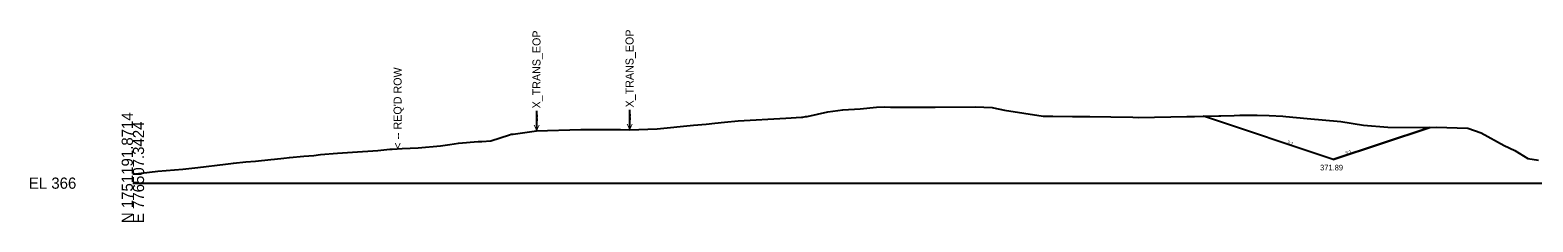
# Model space of a CAD drawing. Extents: x 776426 to 854588, y 1736205 to 1756790.
# Drawn here: x 805845.1 to 806220.7, y 1738705.1 to 1738753 of the extents above; entities that cross this region are included whole.
import ezdxf

# ---------------------------------------------------------------- set-up
doc = ezdxf.new("R2010")
doc.units = 0
for name, color, linetype in [('DTM CONTOURS_MAJOR_TX', 7, 'Continuous'), ('DTM_X_FLOW_ARROWS', 7, 'Continuous'), ('X_TRANS_EOP', 7, 'Continuous'), ('XS_M_SHAPES_EARTHWORK', 7, 'Continuous'), ('XS_P_FINISHED_GRADE', 7, 'Continuous'), ('XS_P_ROW', 7, 'Continuous'), ('XS_P_TX_DCH', 7, 'Continuous'), ('XS_P_TX_FS_BS', 7, 'Continuous'), ('XS_X_PAVEMENT', 7, 'Continuous')]:
    doc.layers.add(name, color=color, linetype=linetype)

msp = doc.modelspace()

# ---------------------------------------------------------------- linework, layer by layer
at = {"layer": 'DTM CONTOURS_MAJOR_TX'}
msp.add_line((805870.79, 1738714.76), (806370.79, 1738714.76), dxfattribs=at)
at = {"layer": 'DTM_X_FLOW_ARROWS'}
msp.add_lwpolyline([(805870.79, 1738716.99), (805877.07, 1738717.73), (805883.26, 1738718.29), (805887.07, 1738718.7), (805893.93, 1738719.48), (805895.96, 1738719.75), (805899.04, 1738720.09), (805901.42, 1738720.27), (805905.3, 1738720.68), (805906.17, 1738720.74), (805908.51, 1738720.99), (805909.98, 1738721.18), (805913.48, 1738721.54), (805915.98, 1738721.7), (805917.67, 1738721.89), (805921.95, 1738722.23), (805925.67, 1738722.52), (805932.01, 1738722.95), (805935, 1738723.24), (805935.57, 1738723.29), (805938.13, 1738723.4), (805942.09, 1738723.61), (805947.69, 1738724.1), (805950.03, 1738724.43), (805952.16, 1738724.76), (805957.1, 1738725.14), (805958.01, 1738725.18), (805960.29, 1738725.35), (805964.95, 1738726.86), (805965.38, 1738726.99), (805965.81, 1738727.04), (805971.67, 1738727.87), (805982.74, 1738728.13), (805983.23, 1738728.14), (805983.58, 1738728.14), (805984.55, 1738728.14), (805992.69, 1738728.13), (805994.92, 1738728.11), (806001.81, 1738728.34), (806010.92, 1738729.23), (806014.09, 1738729.53), (806016.27, 1738729.77), (806018.68, 1738729.99), (806022.1, 1738730.35), (806034.01, 1738730.99), (806037.88, 1738731.25), (806038.26, 1738731.26), (806038.91, 1738731.38), (806039.31, 1738731.44), (806044.51, 1738732.6), (806048.25, 1738733.08), (806052.55, 1738733.32), (806056.62, 1738733.74), (806058.71, 1738733.86), (806060.12, 1738733.77), (806071.32, 1738733.74), (806081.34, 1738733.82), (806083.44, 1738733.78), (806085.54, 1738733.66), (806085.86, 1738733.58), (806088.65, 1738733.02), (806098.32, 1738731.53), (806099.03, 1738731.53), (806099.85, 1738731.54), (806100.3, 1738731.52), (806100.74, 1738731.5), (806105.63, 1738731.45), (806109.96, 1738731.43), (806115.24, 1738731.36), (806120.7, 1738731.24), (806122.12, 1738731.17), (806134.17, 1738731.44), (806136.13, 1738731.4), (806146.05, 1738731.69), (806147.49, 1738731.73), (806150.87, 1738731.79), (806151.77, 1738731.79), (806154.8, 1738731.67), (806158.16, 1738731.48), (806158.93, 1738731.43), (806164.27, 1738730.95), (806172.72, 1738730.14), (806178.32, 1738729.25), (806184.43, 1738728.79), (806193.19, 1738728.65), (806196.5, 1738728.74), (806204.41, 1738728.54), (806207.75, 1738727.3), (806213.5, 1738724.14), (806216.14, 1738722.92), (806219.47, 1738720.93), (806222.08, 1738720.47)], dxfattribs=at)
at = {"layer": 'X_TRANS_EOP'}
for p, q in [((805971.67, 1738732.87), (805971.67, 1738727.87)), ((805971.67, 1738732.87), (805971.67, 1738727.87)), ((805994.92, 1738733.11), (805994.92, 1738728.11)), ((805994.92, 1738733.11), (805994.92, 1738728.11))]:
    msp.add_line(p, q, dxfattribs=at)
at = {"layer": 'XS_M_SHAPES_EARTHWORK'}
msp.add_lwpolyline([(806154.8, 1738731.67), (806158.16, 1738731.48), (806158.93, 1738731.43), (806164.27, 1738730.95), (806172.72, 1738730.14), (806178.32, 1738729.25), (806184.43, 1738728.79), (806193.19, 1738728.65), (806194.94, 1738728.7), (806170.79, 1738720.65), (806138.35, 1738731.47), (806146.05, 1738731.69), (806147.49, 1738731.73), (806150.87, 1738731.79), (806151.77, 1738731.79)], close=True, dxfattribs=at)
at = {"layer": 'XS_P_FINISHED_GRADE'}
for q in [(806138.35, 1738731.47), (806194.94, 1738728.7)]:
    msp.add_line((806170.79, 1738720.65), q, dxfattribs=at)

# ---------------------------------------------------------------- texts
at = {"layer": 'DTM CONTOURS_MAJOR_TX'}
for s, p in [('N 1751191.8714', (805870.79, 1738704.76)), ('E 776507.3424', (805873.59, 1738704.76))]:
    msp.add_text(s, height=2.8, rotation=90, dxfattribs=at).set_placement(p)
msp.add_text('EL 366', height=2.8, dxfattribs=at).set_placement((805844.79, 1738713.36))
at = {"layer": 'XS_P_ROW'}
msp.add_text("< -- REQ'D ROW", height=2, rotation=90, dxfattribs=at).set_placement((805937.95, 1738723.35))
at = {"layer": 'XS_P_TX_DCH'}
msp.add_text('371.89', height=1.4, dxfattribs=at).set_placement((806167.51, 1738717.95))
at = {"layer": 'XS_P_TX_FS_BS'}
for rotation, p in [(341.5651, (806159.21, 1738724.71)), (18.4349, (806173.99, 1738721.87))]:
    msp.add_text('3:1', height=0.8, rotation=rotation, dxfattribs=at).set_placement(p)
at = {"layer": 'XS_X_PAVEMENT'}
for p in [(805972.67, 1738727.87), (805995.92, 1738728.11)]:
    msp.add_text('< --  X_TRANS_EOP', height=2, rotation=90, dxfattribs=at).set_placement(p)

doc.saveas('drawing.dxf')
